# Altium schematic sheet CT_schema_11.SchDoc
size 389 x 385 mm
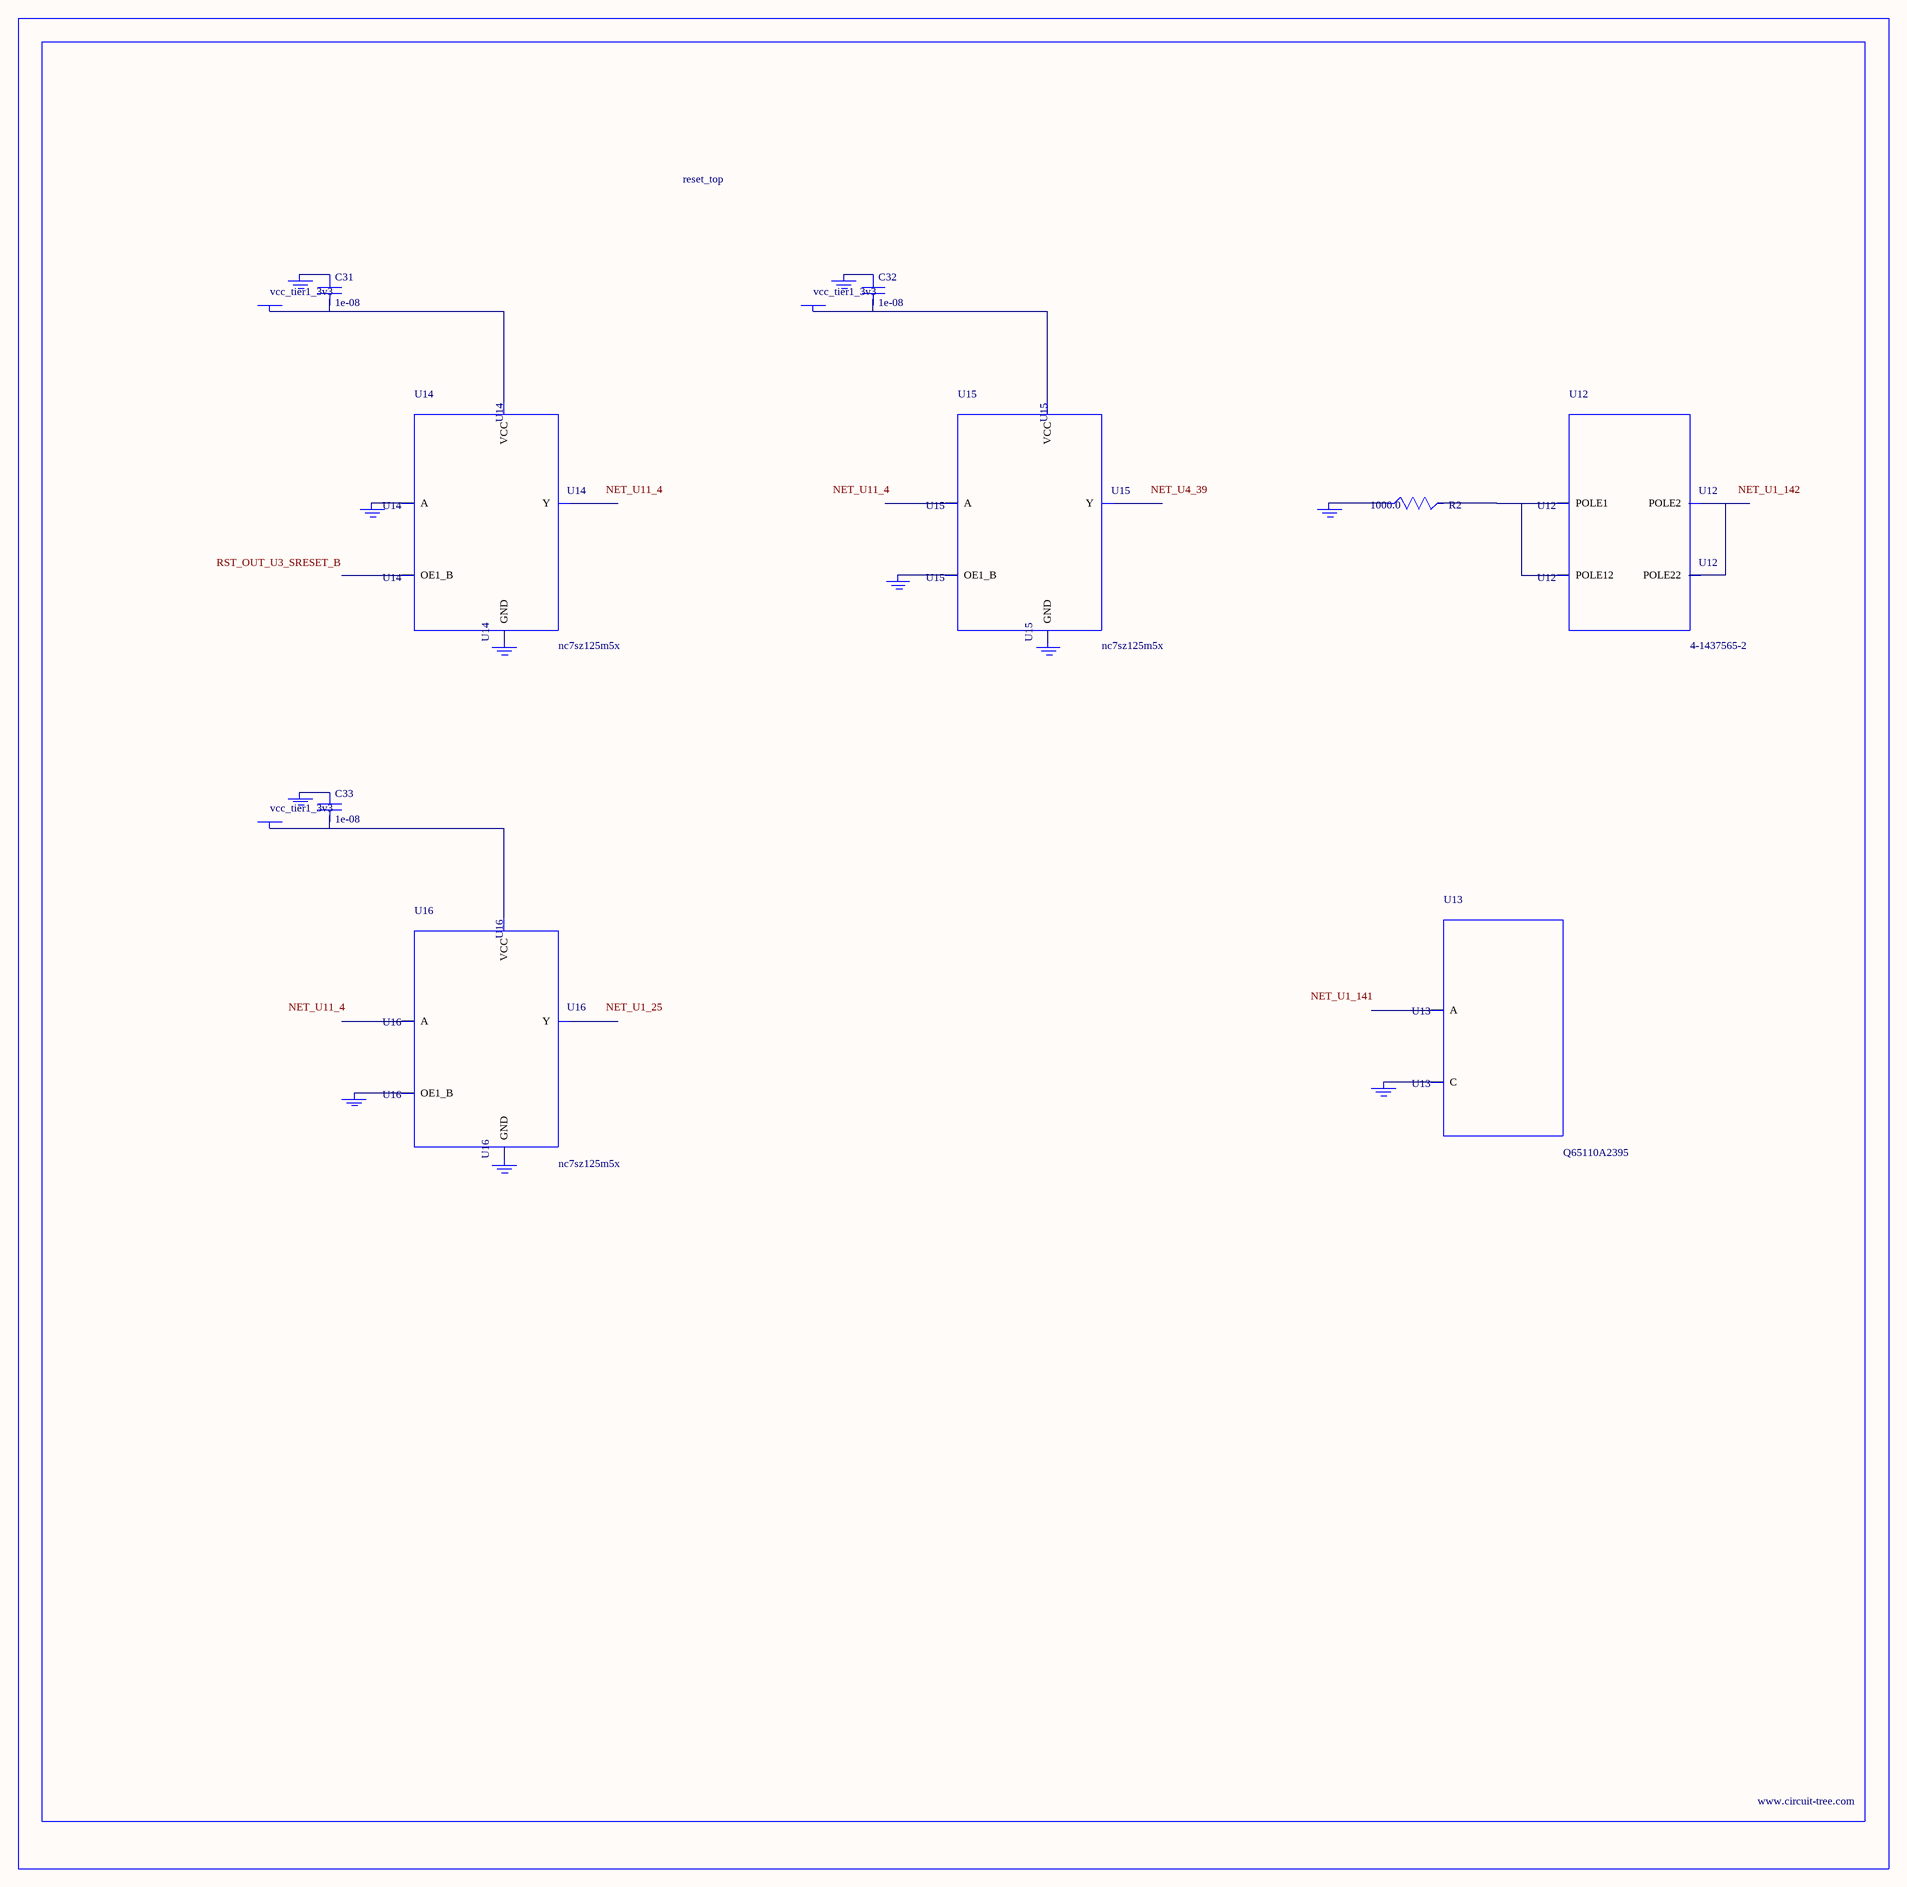
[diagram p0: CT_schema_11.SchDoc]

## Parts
BORDER10  (no value)
C31  1e-08  [C0402]
C32  1e-08  [C0402]
C33  1e-08  [C0402]
GND_INSTANCE_10_0  (no value)
GND_INSTANCE_10_1  (no value)
GND_INSTANCE_10_2  (no value)
GND_INSTANCE_10_3  (no value)
GND_INSTANCE_10_4  (no value)
GND_INSTANCE_10_5  (no value)
GND_INSTANCE_10_6  (no value)
GND_INSTANCE_10_7  (no value)
GND_INSTANCE_10_8  (no value)
GND_INSTANCE_10_9  (no value)
GND_INSTANCE_10_10  (no value)
POWER_INSTANCE_10_0  vcc_tier1_3v3
POWER_INSTANCE_10_1  vcc_tier1_3v3
POWER_INSTANCE_10_2  vcc_tier1_3v3
R2  1000.0  [R0603]
U12  4-1437565-2  [SW_4-1437565-2]
U13  Q65110A2395  [LGM67K-G1J2-24-Z]
U14  nc7sz125m5x  [NC7SZ125M5X]
U15  nc7sz125m5x  [NC7SZ125M5X]
U16  nc7sz125m5x  [NC7SZ125M5X]

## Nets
NetC31_1: C31.1 GND_INSTANCE_10_2.0(GND)
NetC31_2: C31.2 POWER_INSTANCE_10_0.0(PWR) U14.5(VCC)
NetC32_1: C32.1 GND_INSTANCE_10_5.0(GND)
NetC32_2: C32.2 POWER_INSTANCE_10_1.0(PWR) U15.5(VCC)
NetC33_1: C33.1 GND_INSTANCE_10_8.0(GND)
NetC33_2: C33.2 POWER_INSTANCE_10_2.0(PWR) U16.5(VCC)
NetGND_INSTANCE_10_0_0: GND_INSTANCE_10_0.0(GND) R2.1
NetGND_INSTANCE_10_1_0: GND_INSTANCE_10_1.0(GND) U13.C
NetGND_INSTANCE_10_3_0: GND_INSTANCE_10_3.0(GND) U14.2(A)
NetGND_INSTANCE_10_4_0: GND_INSTANCE_10_4.0(GND) U14.3(GND)
NetGND_INSTANCE_10_6_0: GND_INSTANCE_10_6.0(GND) U15.1(OE1_B)
NetGND_INSTANCE_10_7_0: GND_INSTANCE_10_7.0(GND) U15.3(GND)
NetGND_INSTANCE_10_9_0: GND_INSTANCE_10_9.0(GND) U16.1(OE1_B)
NetGND_INSTANCE_10_10_0: GND_INSTANCE_10_10.0(GND) U16.3(GND)
NetR2_2: R2.2 U12.1(POLE1) U12.2(POLE12)
NetU12_3: U12.3(POLE2) U12.4(POLE22)

Not connected (* = marked no-connect by the designer): U13 A; U14 1(OE1_B) 4(Y); U15 2(A) 4(Y); U16 2(A) 4(Y)

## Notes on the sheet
- Labels drawn without touching a wire or pin: NET_U1_25, NET_U1_141, NET_U1_142, NET_U4_39, NET_U11_4, RST_OUT_U3_SRESET_B

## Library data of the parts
BORDER10 = BORDER_PAGE10
C31-C33 = C0402C103K3RAC
GND_INSTANCE_10_0-GND_INSTANCE_10_10 = GND
POWER_INSTANCE_10_0-POWER_INSTANCE_10_2 = PWR
R2 = RC0603JR-071KL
